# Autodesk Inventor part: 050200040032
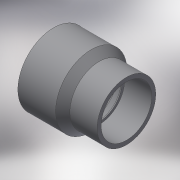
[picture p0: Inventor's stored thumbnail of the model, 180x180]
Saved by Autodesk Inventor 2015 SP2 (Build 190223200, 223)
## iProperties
Created: 2017-10
Part Number: 050200040032
Material: Generic
Description: PLASSON REDUCING SOCKET M.F.40(32)32 CEMENTED
Document SubType Name: Modeling
Designer: KIM
Density: 1 g/cm^3
Appearance: Default
Author: KIM
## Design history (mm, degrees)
derived "050200.ipt"
feature "Solid1::050200.ipt"
tag "TaggingFeature1"
body "Solid1"
other parameters: "d0" = 57, "d1" = 26, "d2" = 29, "d3" = 22, "d4" = 32, "d5" = 39, "d6" = 32, "d8" = 28.8, "d9" = 45 deg, "d12" = 0.32, "d_" = 32, "d_1" = 32, "L_" = 26, "l_" = 22, "l_1" = 29, "E_" = 39, "H_" = 57, "d11" = 2.44979
